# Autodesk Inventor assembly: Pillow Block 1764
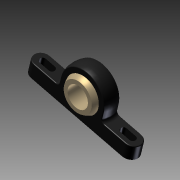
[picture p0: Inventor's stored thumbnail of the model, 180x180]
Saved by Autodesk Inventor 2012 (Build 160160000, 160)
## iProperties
Created: 2009-01
Part Number: Pillow Block 1764
Document SubType Name: Assembly
Designer: lwoods
Mass: 25.286 g
Surface Area: 91.7026 cm^2
Volume: 18.0615 cm^3
Density: 1.4 g/cm^3
Author: lwoods
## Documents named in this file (3)
- R:\CAD Archives\Pillow_Block_1764\Pillow_Block_1764.iam
- R:\CAD Archives\Pillow_Block_1764\Pillow_Block_Outer_Piece_1764.ipt
- R:\CAD Archives\Pillow_Block_1764\Pillow_Block_Inner_Piece_1764.ipt
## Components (2 placed, 2 different names)
1. Pillow_Block_Outer_Piece_1764:1 — Tangent:1, Angle:1, Angle:2
2. Pillow_Block_Inner_Piece_1764:1 — Tangent:1, Angle:1, Mate:1
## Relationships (4: Angle 2, Tangent 1, Mate 1)
- Tangent:1: Pillow_Block_Outer_Piece_1764:1 ↔ Pillow_Block_Inner_Piece_1764:1
- Angle:1: Pillow_Block_Outer_Piece_1764:1 ↔ Pillow_Block_Inner_Piece_1764:1
- Mate:1: Pillow_Block_Inner_Piece_1764:1
- Angle:2: Pillow_Block_Outer_Piece_1764:1
